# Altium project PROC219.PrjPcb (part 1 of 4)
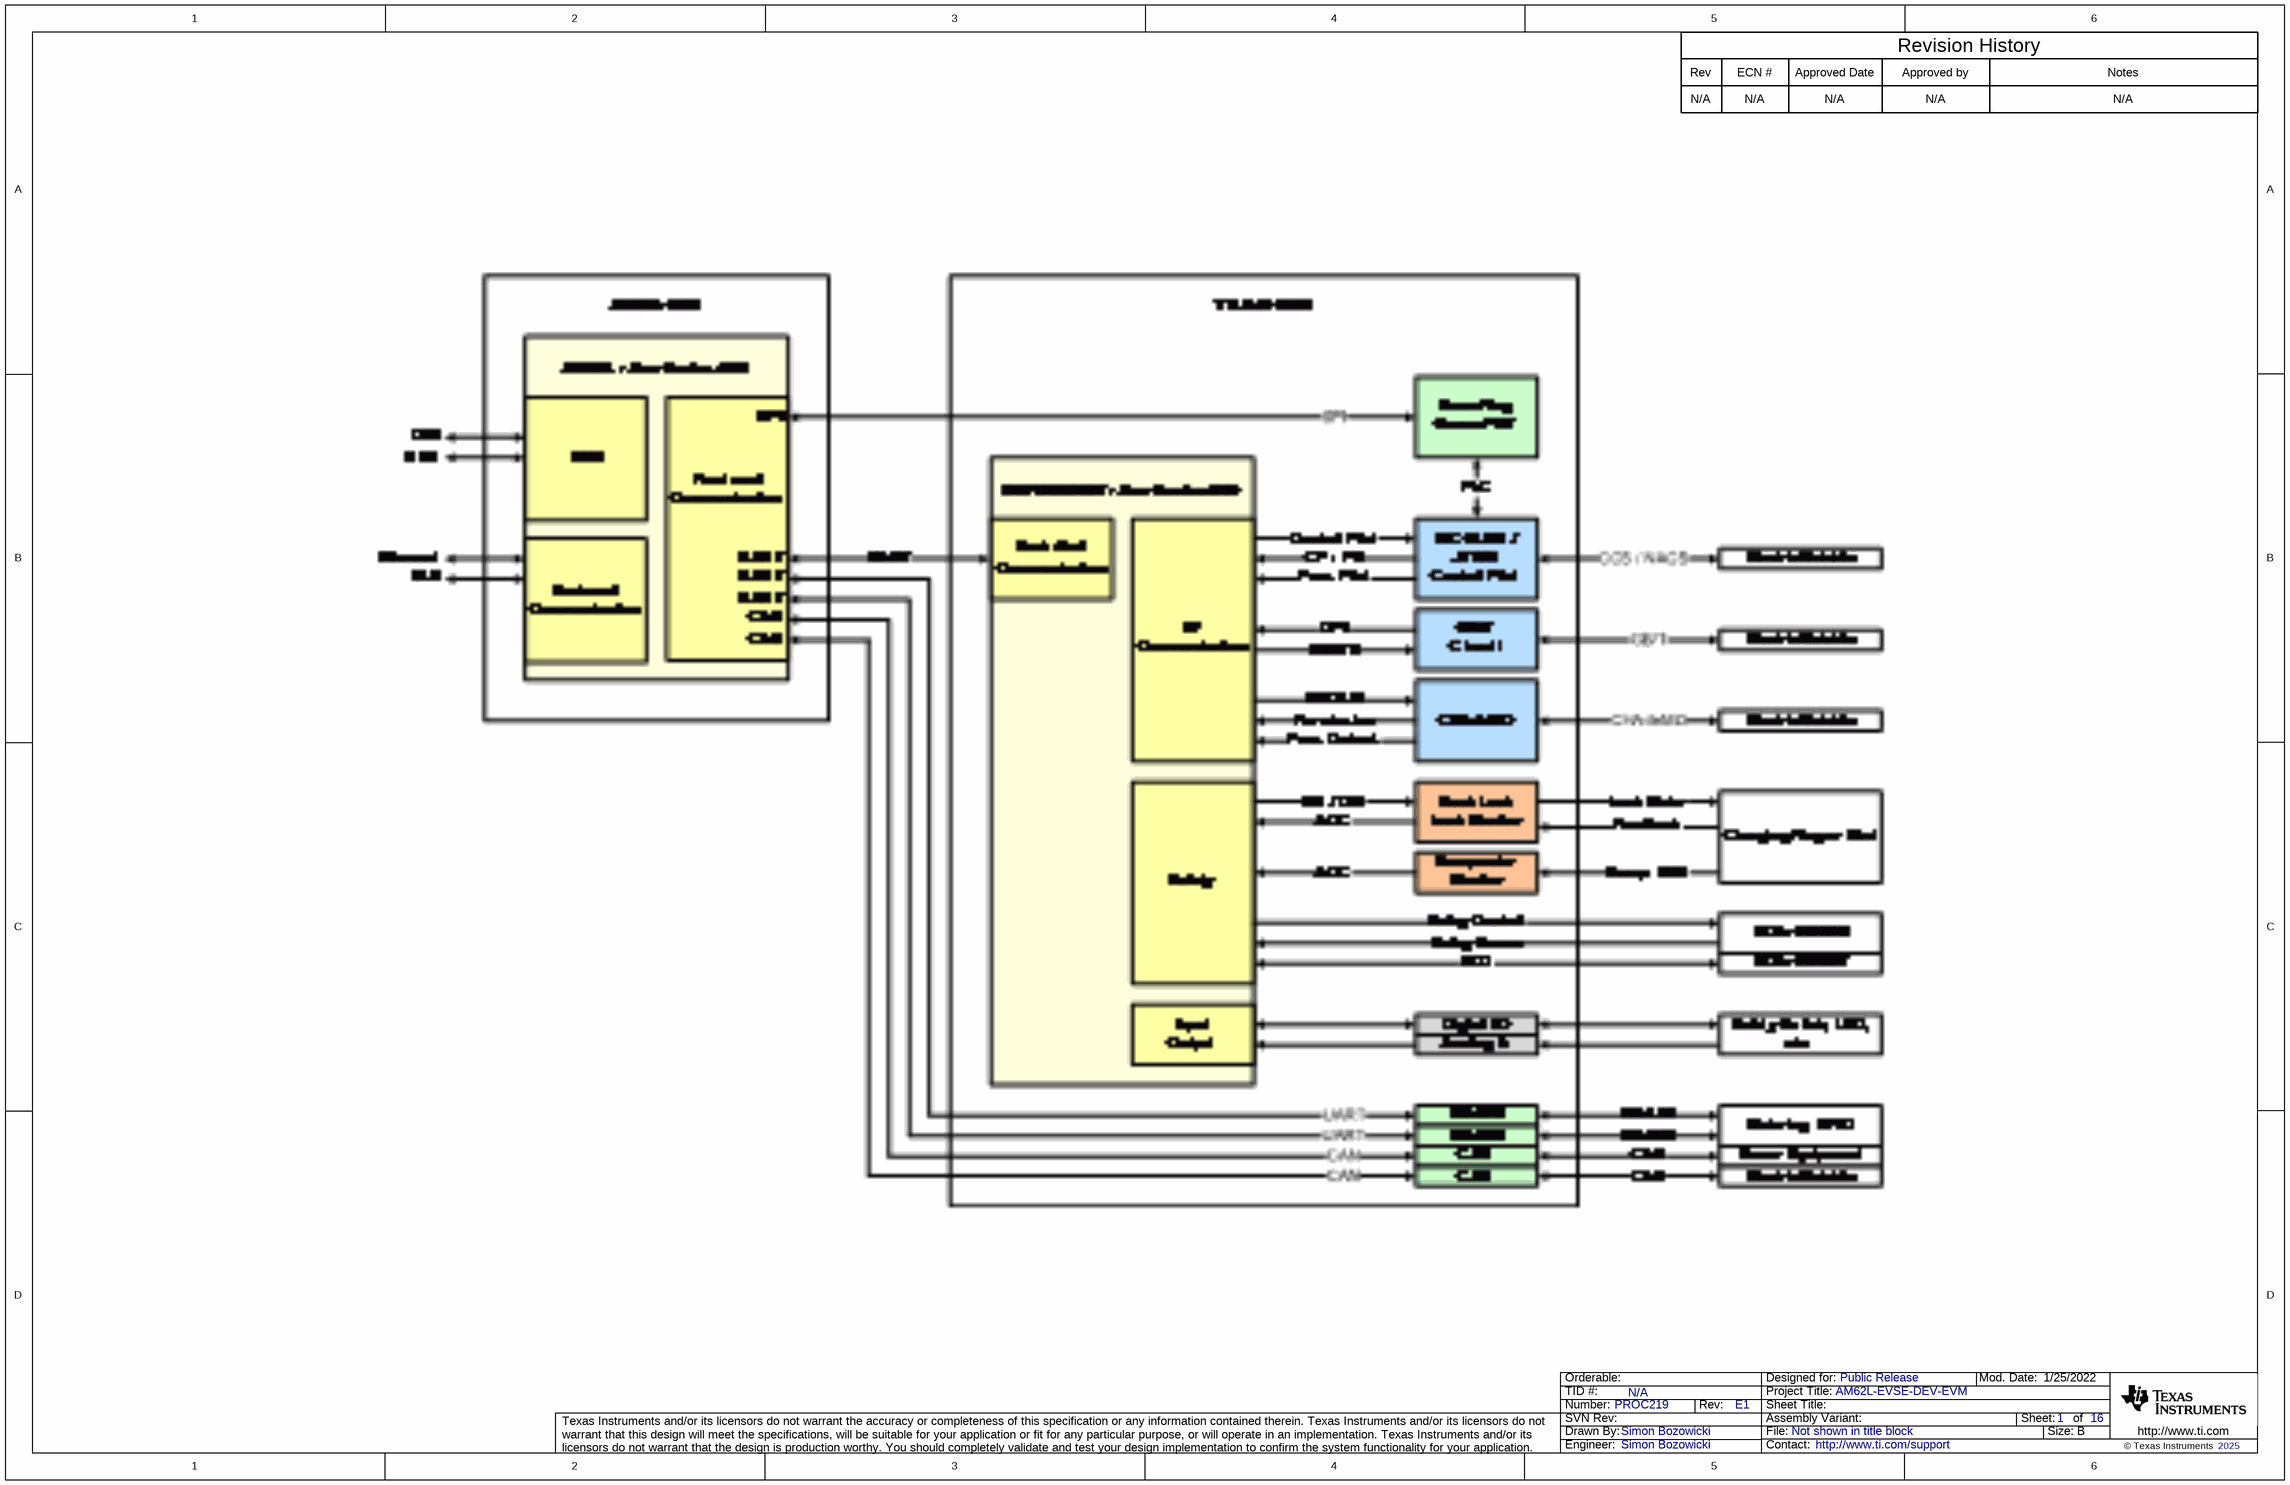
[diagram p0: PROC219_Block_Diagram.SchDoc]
DrawnBy: Simon Bozowicki; TID: N/A; TechSupport: http://www.ti.com/support; SCH_Rev: E1; PRJ_Title: AM62L-EVSE-DEV-EVM; PRJ_Number: PROC219; PRJ_Engineer: Simon Bozowicki; PRJ_Customer: Public Release; PCB_Rev: E1; PCB_Layout: Simon Bozowicki; CopyrightYear: 2025
16 sheets, 580 parts. Net scope: global (net labels, ports and power ports of the same name join across sheets).
Board file: PROC219E1.PcbDoc
Sheets:
  PROC219_Block_Diagram.SchDoc
  PROC219_Power_IN_Dig.SchDoc
  PROC219_Power_Analog.SchDoc
  PROC219_MSPM0.SchDoc
  PROC219_PLC.SchDoc
  PROC219_Pilot_Interface.SchDoc
  PROC219_GBT.SchDoc
  PROC219_CHAdeMO.SchDoc
  PROC219_PluckLock.SchDoc
  PROC219_Temp_Sense.SchDoc
  PROC219_Serial.SchDoc
  PROC219_CAN.SchDoc
  PROC219_IO.SchDoc
  PROC219_XDS110_Debug.SchDoc
  PROC219_Connectors.SchDoc
  PROC219_Hardware.SchDoc

## Sheet PROC219_Block_Diagram.SchDoc
size 431 x 279 mm; Date: Not shown in title block; ApprovedBy: Not shown in title block; CheckedBy: Not shown in title block; Author: Not shown in title block; CompanyName: Not shown in title block; Engineer: Not shown in title block; Organization: Not shown in title block; Address1: Not shown in title block; Address2: Not shown in title block; Address3: Not shown in title block; Address4: Not shown in title block; DocumentNumber: 1; Revision: Use project parameter SCH_Rev; SheetNumber: 1; SheetTotal: 16; PageSetup: Record=PageOptions¦CenterHorizontal=True¦CenterVertical=True¦PrintScale=1.00¦XCorrection=1.00¦YCorrection=1.00¦PrintKind=0¦BorderSize=5000000¦LeftOffset=0¦BottomOffset=0¦Orientation=2¦PaperLength=1000¦PaperWidth=1000¦Scale=100¦PaperSource=15¦PrintQuality=600¦MediaType=1¦DitherType=10¦PaperKind=Letter¦PrintScaleMode=1

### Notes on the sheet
- Rev
- N/A
- ECN #
- Approved Date
- Approved by
- Revision History
- Notes

## Sheet PROC219_Power_IN_Dig.SchDoc
size 431 x 279 mm; Date: Not shown in title block; ApprovedBy: Not shown in title block; CheckedBy: Not shown in title block; Author: Not shown in title block; CompanyName: Not shown in title block; Engineer: Not shown in title block; Organization: Not shown in title block; Address1: Not shown in title block; Address2: Not shown in title block; Address3: Not shown in title block; Address4: Not shown in title block; DocumentNumber: 1; Revision: Use project parameter SCH_Rev; SheetNumber: 2; SheetTotal: 16; PageSetup: Record=PageOptions¦CenterHorizontal=True¦CenterVertical=True¦PrintScale=1.00¦XCorrection=1.00¦YCorrection=1.00¦PrintKind=0¦BorderSize=5000000¦LeftOffset=0¦BottomOffset=0¦Orientation=2¦PaperLength=1000¦PaperWidth=1000¦Scale=100¦PaperSource=15¦PrintQuality=600¦MediaType=1¦DitherType=10¦PaperKind=Letter¦PrintScaleMode=1
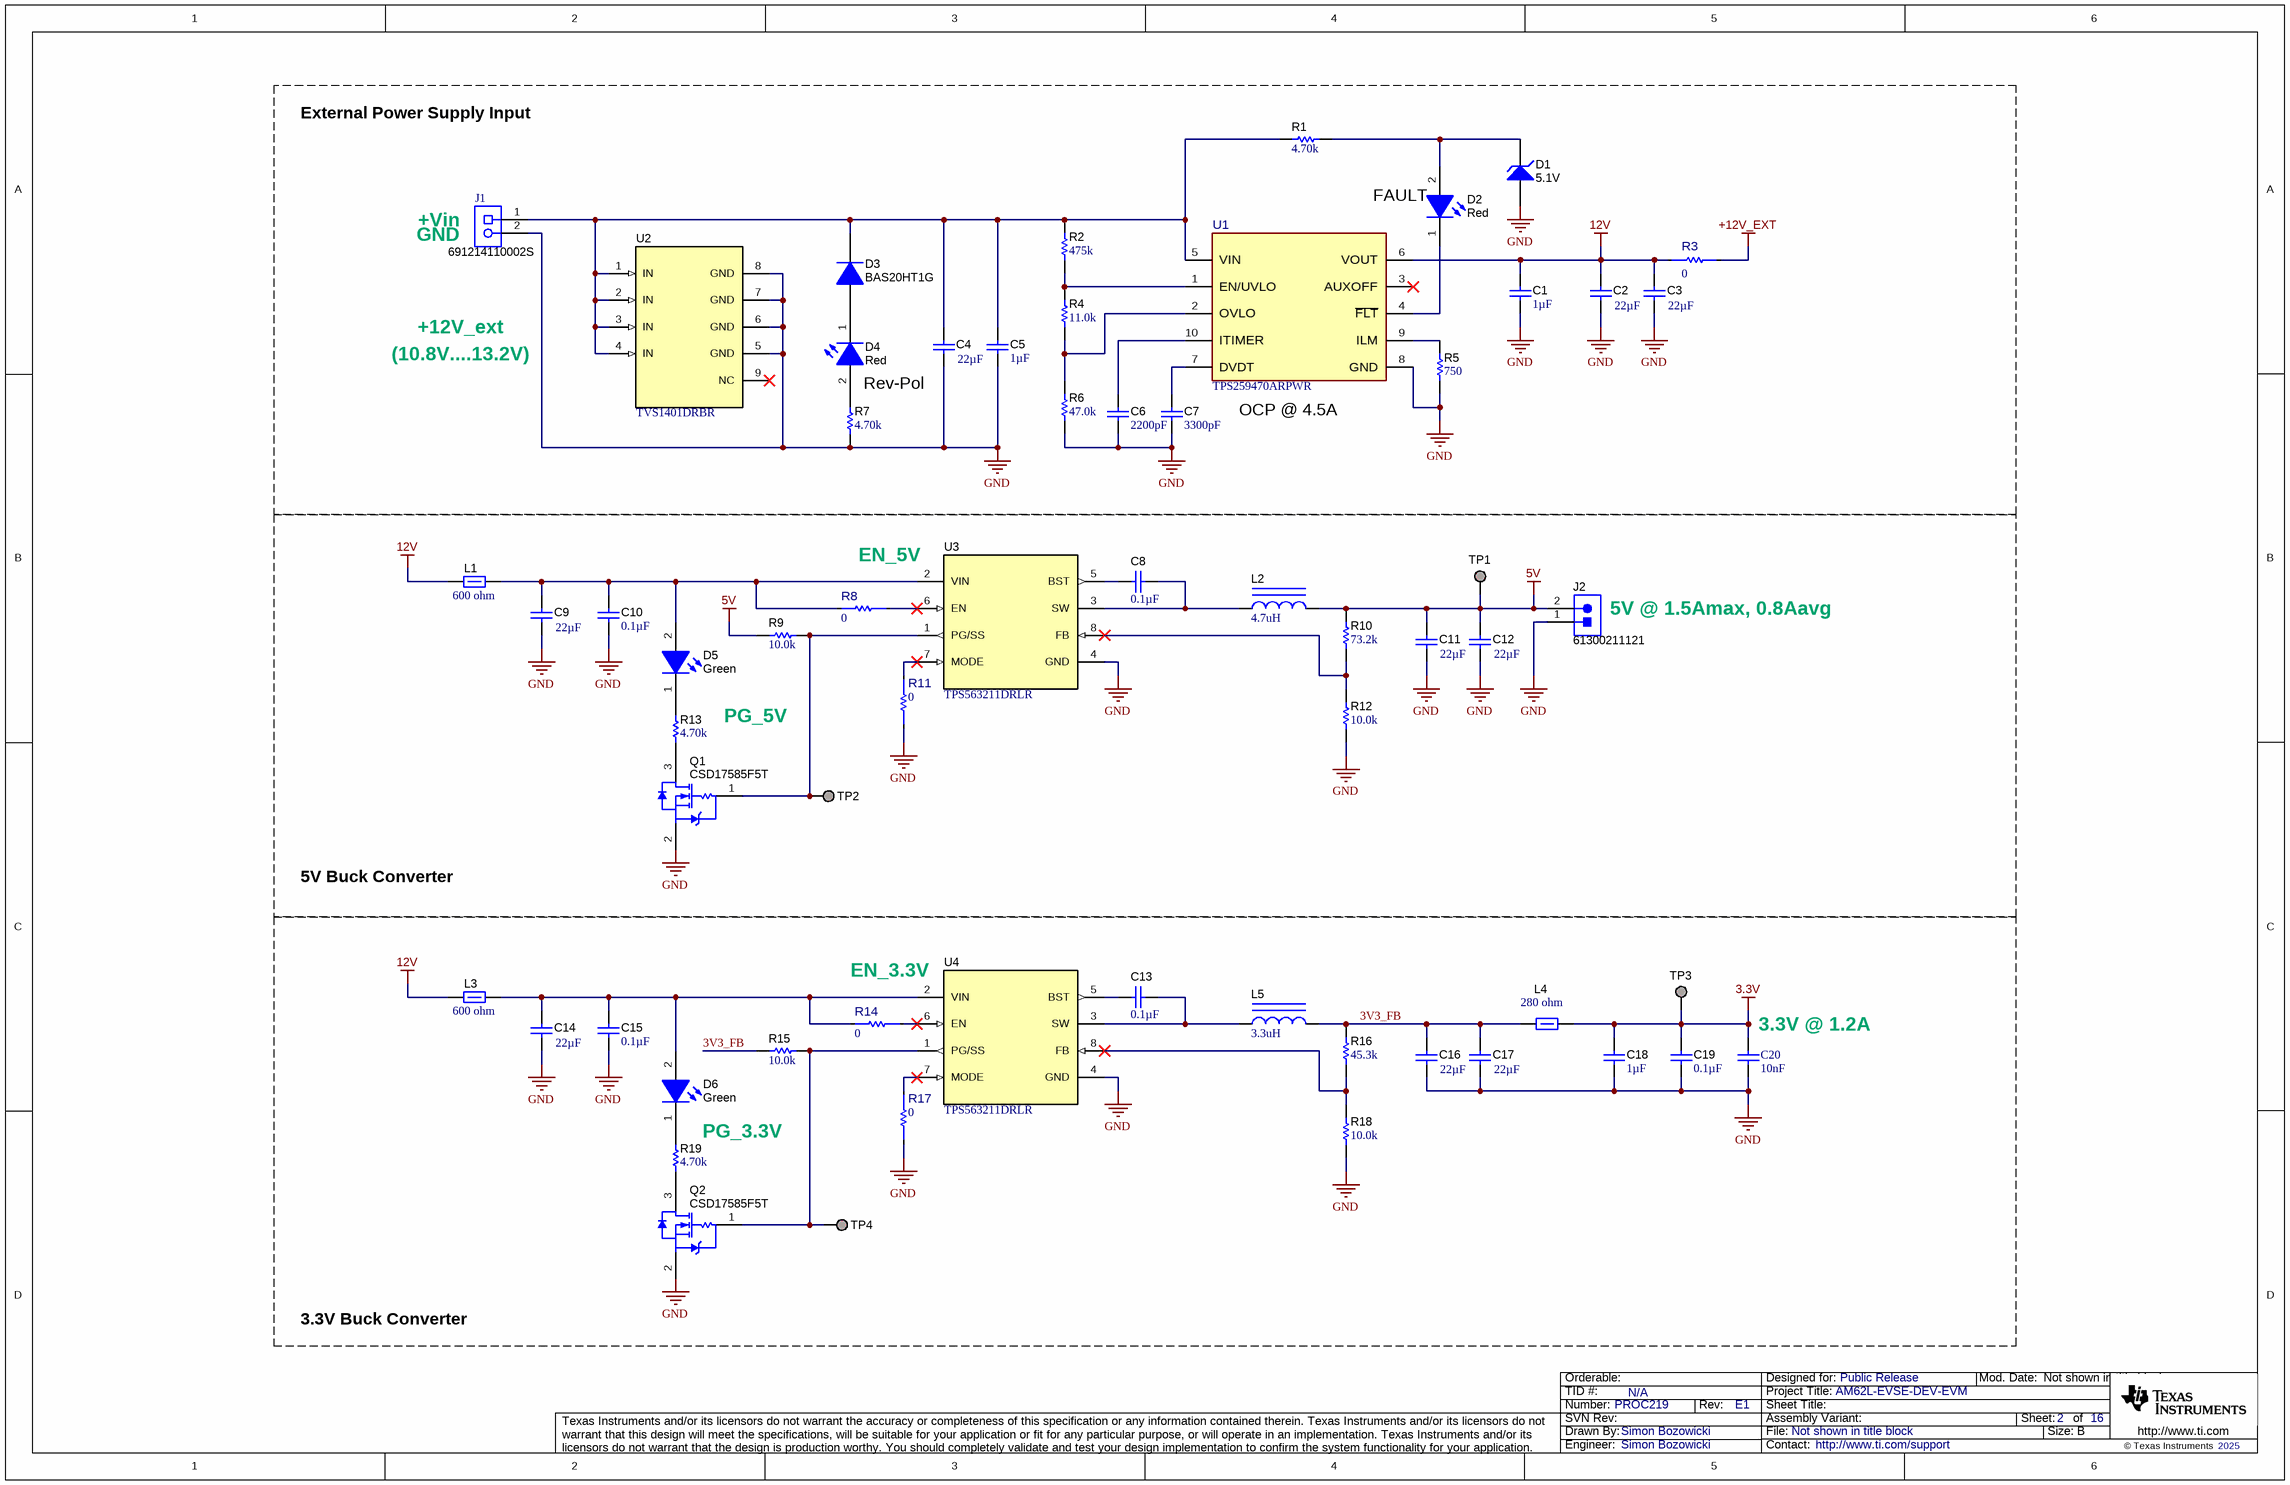
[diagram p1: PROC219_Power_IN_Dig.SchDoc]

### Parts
C1  Cap_F: 1µF  [0603]  (hidden comment: C1608X7R1E105K080AB)
C2  ValueDisplayed: 22µF  [1210_270]  (hidden comment: CC1210KKX7R8BB226)
C3  ValueDisplayed: 22µF  [1210_270]  (hidden comment: CC1210KKX7R8BB226)
C4  ValueDisplayed: 22µF  [1210_270]  (hidden comment: CC1210KKX7R8BB226)
C5  Cap_F: 1µF  [0603]  (hidden comment: C1608X7R1E105K080AB)
C6  ValueDisplayed: 2200pF  [0402]  (hidden comment: CL05B222JB5NNNC)
C7  ValueDisplayed: 3300pF  [0402]  (hidden comment: GRM155R71H332KA01D)
C8  ValueDisplayed: 0.1µF  [0402]  (hidden comment: CC0402KRX7R8BB104)
C9  ValueDisplayed: 22µF  [1210_270]  (hidden comment: CC1210KKX7R8BB226)
C10  ValueDisplayed: 0.1µF  [0402]  (hidden comment: CC0402KRX7R8BB104)
C11  ValueDisplayed: 22µF  [1210_270]  (hidden comment: CC1210KKX7R8BB226)
C12  ValueDisplayed: 22µF  [1210_270]  (hidden comment: CC1210KKX7R8BB226)
C13  ValueDisplayed: 0.1µF  [0402]  (hidden comment: CC0402KRX7R8BB104)
C14  ValueDisplayed: 22µF  [1210_270]  (hidden comment: CC1210KKX7R8BB226)
C15  ValueDisplayed: 0.1µF  [0402]  (hidden comment: CC0402KRX7R8BB104)
C16  ValueDisplayed: 22µF  [1210_270]  (hidden comment: CC1210KKX7R8BB226)
C17  ValueDisplayed: 22µF  [1210_270]  (hidden comment: CC1210KKX7R8BB226)
C18  Cap_F: 1µF  [0603]  (hidden comment: C1608X7R1E105K080AB)
C19  ValueDisplayed: 0.1µF  [0402]  (hidden comment: CC0402KRX7R8BB104)
C20  value 10nF  [WCAP-CSGP_0402_L1W0.5H0.5]  (hidden comment: 885012205050)
D1  value 5.1V  [SOD-523]  (hidden comment: BZT52C5V1T-7)
D2  value Red  [WL-SMCW_RED]  (hidden comment: 150060RS75000)
D3  BAS20HT1G  [SOD-323]
D4  value Red  [WL-SMCW_RED]  (hidden comment: 150060RS75000)
D5  value Green  [WL-SMCW_GREEN]  (hidden comment: 150060VS75000)
D6  value Green  [WL-SMCW_GREEN]  (hidden comment: 150060VS75000)
J1  691214110002S  [FP-691214110002S_HDR2-MFG]
J2  61300211121  [WURTH_61300211121]
L1  value 600 ohm  [1206]  (hidden comment: 74279221601)
L2  ValueDisplayed: 4.7uH  [WE-HC4]  (hidden comment: 744311470)
L3  value 600 ohm  [1206]  (hidden comment: 74279221601)
L4  value 280 ohm  [1206]  (hidden comment: 74279221281)
L5  ValueDisplayed: 3.3uH  [WE-LHMI_7050]  (hidden comment: 74437349033)
Q1  CSD17585F5T  [YJK0003A]
Q2  CSD17585F5T  [YJK0003A]
R1  ValueDisplayed: 4.70k  [0402]  (hidden comment: ERJ-2RKF4701X)
R2  ValueDisplayed: 475k  [0402]  (hidden comment: CRCW0402475KFKED)
R3  value 0  [FP-CRCW12060000Z0EAC_1206-MFG]  (hidden comment: CRCW12060000Z0EAC)
R4  ValueDisplayed: 11.0k  [0402]  (hidden comment: CRCW040211K0FKED)
R5  ValueDisplayed: 750  [0402]  (hidden comment: CRCW0402750RFKED)
R6  ValueDisplayed: 47.0k  [0402]  (hidden comment: RC0402FR-0747KL)
R7  ValueDisplayed: 4.70k  [0402]  (hidden comment: ERJ-2RKF4701X)
R8  value 0  [FP-CRG0402ZR_0402-IPC_C]  (hidden comment: CRG0402ZR)
R9  ValueDisplayed: 10.0k  [0402]  (hidden comment: ERJ-2RKF1002X)
R10  ValueDisplayed: 73.2k  [0402]  (hidden comment: CRCW040273K2FKED)
R11  value 0  [FP-CRG0402ZR_0402-IPC_C]  (hidden comment: CRG0402ZR)
R12  ValueDisplayed: 10.0k  [0402]  (hidden comment: ERJ-2RKF1002X)
R13  ValueDisplayed: 4.70k  [0402]  (hidden comment: ERJ-2RKF4701X)
R14  value 0  [FP-CRG0402ZR_0402-IPC_C]  (hidden comment: CRG0402ZR)
R15  ValueDisplayed: 10.0k  [0402]  (hidden comment: ERJ-2RKF1002X)
R16  ValueDisplayed: 45.3k  [0402S]  (hidden comment: RC0402FR-0745K3L)
R17  value 0  [FP-CRG0402ZR_0402-IPC_C]  (hidden comment: CRG0402ZR)
R18  ValueDisplayed: 10.0k  [0402]  (hidden comment: ERJ-2RKF1002X)
R19  ValueDisplayed: 4.70k  [0402]  (hidden comment: ERJ-2RKF4701X)
TP1  TP_SM_1MM  [TP_SM_1MM]  (value not drawn)  (no BOM)
TP2  TP_SM_1MM  [TP_SM_1MM]  (value not drawn)  (no BOM)
TP3  TP_SM_1MM  [TP_SM_1MM]  (value not drawn)  (no BOM)
TP4  TP_SM_1MM  [TP_SM_1MM]  (value not drawn)  (no BOM)
U1  TPS259470ARPWR  [RPW0010A-MFG]
U2  TVS1401DRBR  [DRB0008A]
U3  TPS563211DRLR  [DRL0008A]
U4  TPS563211DRLR  [DRL0008A]

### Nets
3.3V: C18.1 C19.1 C20.1 L4.2 TP3.1
5V: C11.2 C12.2 J2.2 L2.2 R9.2 R10.2 TP1.1
12V: C1.1 C2.2 C3.2 L1.1 L3.1 R3.1 U1.6(VOUT)
+12V_EXT: R3.2
GND: C1.2 C2.1 C3.1 C4.1 C5.2 C6.2 C7.2 C9.1 C10.2 C11.1 C12.1 C14.1 C15.2 C16.1 C17.1 C18.2 C19.2 C20.2 D1.2(A) J1.2 J2.1 Q1.2(S) Q2.2(S) R5.1 R6.1 R7.2 R11.2 R12.1 R17.2 R18.1 U1.8(GND) U2.5(GND) U2.6(GND) U2.7(GND) U2.8(GND) U3.4(GND) U4.4(GND)
3V3_FB: C16.2 C17.2 L4.1 L5.2 R15.2 R16.2
NetC4_2: C4.2 C5.1 D3.1(K) J1.1 R1.2 R2.2 U1.5(VIN) U2.1(IN) U2.2(IN) U2.3(IN) U2.4(IN)
NetC6_1: C6.1 U1.10(ITIMER)
NetC7_1: C7.1 U1.7(DVDT)
NetC8_1: C8.1 U3.5(BST)
NetC8_2: C8.2 L2.1 U3.3(SW)
NetC9_2: C9.2 C10.1 D5.2(A) L1.2 R8.2 U3.2(VIN)
NetC13_1: C13.1 U4.5(BST)
NetC13_2: C13.2 L5.1 U4.3(SW)
NetC14_2: C14.2 C15.1 D6.2(A) L3.2 R14.2 U4.2(VIN)
NetD1_1: D1.1(K) D2.2(A) R1.1
NetD2_1: D2.1(K) U1.4(~{FLT})
NetD3_2: D3.2(A) D4.1(K)
NetD4_2: D4.2(A) R7.1
NetD5_1: D5.1(K) R13.1
NetD6_1: D6.1(K) R19.1
NetQ1_1: Q1.1(G) R9.1 TP2.1 U3.1(PG/SS)
NetQ1_3: Q1.3(D) R13.2
NetQ2_1: Q2.1(G) R15.1 TP4.1 U4.1(PG/SS)
NetQ2_3: Q2.3(D) R19.2
NetR2_1: R2.1 R4.2 U1.1(EN/UVLO)
NetR4_1: R4.1 R6.2 U1.2(OVLO)
NetR5_2: R5.2 U1.9(ILM)
NetR8_1: R8.1 U3.6(EN)
NetR10_1: R10.1 R12.2 U3.8(FB)
NetR11_1: R11.1 U3.7(MODE)
NetR14_1: R14.1 U4.6(EN)
NetR16_1: R16.1 R18.2 U4.8(FB)
NetR17_1: R17.1 U4.7(MODE)

Not connected (* = marked no-connect by the designer): U1 3(AUXOFF)*; U2 9(NC)*

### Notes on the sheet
- External Power Supply Input
- (near J1) +Vin
- (near D2) FAULT
- (near J1) GND
- +12V_ext
- (10.8V....13.2V)
- Rev-Pol
- (near U1) OCP @ 4.5A
- EN_5V
- (near J2) 5V @ 1.5Amax, 0.8Aavg
- PG_5V
- 5V Buck Converter
- (near U4) EN_3.3V
- (near C20) 3.3V @ 1.2A
- PG_3.3V
- 3.3V Buck Converter

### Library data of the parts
C1 C5 C18 = CMP-0007040-4: CAP, CERM, 1 uF, 25 V, +/- 10%, X7R, 0603; Manufacturer: TDK; TaMin_C: -55°C; Polarized: N; SizeAreaWB_mm2: 4.68; Value1: Unknown; U/M: EA; Value: 1uF; TaMax_C: 125°C; SizeZ_mm: 1; SizeX_mm: 1.6; SizeY_mm: 0.8; Value2: 25V; SizeArea_mm2: 1.28; AEC Category: Q200
C2-C4 C9 C11 C12 C14 C16 C17 = CMP-0082267-1: CAP, CERM, 22 µF, 25 V,+/- 10%, X7R, 1210; Manufacturer: Yageo; TaMin_C: -55°C; ESR_ohm: 1m; Polarized: N; SizeAreaWB_mm2: 14.7; Value1: 0.001 ohm; U/M: EA; Value: 22uF; TaMax_C: 125°C; SizeZ_mm: 2.7; SizeX_mm: 3.2; SizeY_mm: 2.5; Cap_Case: 1210; Value2: 25V; SizeArea_mm2: 8; AEC Category: Q200
C6 = CMP-0006344-2: CAP, CERM, 2200 pF, 50 V, +/- 5%, X7R, 0402; Manufacturer: Samsung Electro-Mechanics; TaMin_C: -55°C; Polarized: N; SizeAreaWB_mm2: 3; Value1: Unknown; U/M: EA; Value: 2200pF; TaMax_C: 125°C; SizeZ_mm: 0.6; SizeX_mm: 1; SizeY_mm: 0.5; Value2: 50V; Cap_F: 2.2nF; AEC Category: Q200
C7 = CMP-0006688-2: CAP, CERM, 3300 pF, 50 V, +/- 10%, X7R, 0402; Manufacturer: MuRata; TaMin_C: -55°C; Polarized: N; SizeAreaWB_mm2: 3; Value1: Unknown; U/M: EA; Value: 3300pF; TaMax_C: 125°C; SizeZ_mm: 0.6; SizeX_mm: 1; SizeY_mm: 0.5; Value2: 50V; Cap_F: 3.3nF; AEC Category: Q200
C8 C10 C13 C15 C19 = CMP-0860555-1: CAP, CERM, 0.1 µF, 25 V,+/- 10%, X7R, 0402; Manufacturer: Yageo; SizeArea_mm2: 0.5; AEC Qualified: N; SizeX_mm: 1; U/M: EA; Value: 0.1uF; TaMin_C: -55°C; VDC_V: 25V; SizeZ_mm: 0.6; Cap_F: 100nF; TaMax_C: 125°C; SizeAreaWB_mm2: 3; AEC Category: Q200
C20 = CMP-0052806-1: WCAP-CSGP Multilayer Ceramic Chip Capacitor, General Purpose, size 0402, X7R, 10nF, 25VDC; Manufacturer: Wurth Elektronik; Capacitance Tolerance: +/-10%; Dissipation Factor: 3.5%; Insulation Resistance: 10GOhm; Rated Voltage (DC): 25V; Technical Reference: X7R0402103K025DFCT10000
D1 = CMP-0005899-4: Diode, Zener, 5.1 V, 300 mW, SOD-523; Manufacturer: Diodes Inc.; Power_W: 300mW; Value1: 0.3W; SizeZ_mm: 0.65; AEC Category: Q101; SizeX_mm: 1.7; RJA_CperW: 417; SizeArea_mm2: 1.53; SizeY_mm: 0.9; SizeAreaWB_mm2: 5.13
D2 D4 = CMP-0002947-3: LED, Red, SMD; Manufacturer: Wurth Elektronik; Value1: 0.072W; Vf_V: 2V; Angle: 140; Tjmax_C: 85°C; Type: AlInGaP; Vr_V: 5V; Io_A: 30mA; Power_TotalModule: 72mW
D3 = CMP-0029150-2: Diode, Switching, 200 V, 0.2 A, AEC-Q101, SOD-323; Manufacturer: ON Semiconductor; Value2: 1.25V; Value1: 0.2A; SizeZ_mm: 1; Green_REACh: Incomplete; SizeArea_mm2: 3.645; Vr_V: 200V; SizeX_mm: 2.7; TJmax_C: 150°C; Io_A: 200mA; Value: 200V; Green_Lifecycle: Not Set; SizeAreaWB_mm2: 8.695; AEC Qualified: Y; AEC Category: Q101; SizeY_mm: 1.35
D5 D6 = CMP-0002894-2: LED, Green, SMD; Manufacturer: Wurth Elektronik; Type: AlInGaP; Value2: 2V; Io_A: 20mA; Value1: W
J1 = CMP-0093089-2: 2 Position Wire to Board Terminal Block Horizontal with Board 0.138" (3.50mm) Through Hole; Manufacturer: Wurth; ContactFinish: Tin,Nickel; AEC Qualified: No; Max Wire Gauge: 16; Voltage_V: 300V; SizeZ_mm: 9.2mm; Current_A: 10A; DUT-Pitch_mm: 3.5mm; Min Wire Gauge: 30; Conn Gender: Female; Row_Count: 1; Is Female: yes
J2 = CMP-0054794-2: Header, 2.54 mm, 2x1, Gold, TH; Manufacturer: Wurth Elektronik; Shrouded: N; Gender: Male; Green_REACh: Passed; Pitch_mm: 2.54; Green_Lifecycle: Active; Row_Count: 1; Cert_UL: Y
L1 L3 = CMP-0003141-1: Ferrite Bead, 600 ohm @ 100 MHz, 2.5 A, 1206; Manufacturer: Wurth Elektronik; Ztyp@1GHz_Ohm: 83.8; ZTyp@100MHz_Ohm: 600; SizeAreaWB_mm2: 10.92; DCR_ohm: 38m; Value1: 0.038 ohm; Imax_A: 2.5A; SizeZ_mm: 1.35; SizeX_mm: 3.2; SizeY_mm: 1.6; SizeArea_mm2: 5.12
L2 = CMP-0063928-1: Inductor, Shielded Drum Core, Superflux, 4.7 uH, 6 A, 0.02 ohm, SMD; Manufacturer: Wurth Elektronik; Isat: 7A @ 30% inductance drop; Irms: 6A @ 50C rise; Green_Lifecycle: Active; SizeAreaWB_mm2: 80.1; DCR_ohm: 20m; Green_REACh: Passed; Value: 4.7uH; Imax_A: 6A; SizeZ_mm: 4; SizeX_mm: 7; SizeY_mm: 6.9; SizeArea_mm2: 48.3; Ind_H: 4.7µH; AEC Category: Q200
L4 = CMP-0003140-1: Ferrite Bead, 280 ohm @ 100 MHz, 3.5 A, 1206; Manufacturer: Wurth Elektronik; Ztyp@1GHz_Ohm: 79.415; ZTyp@100MHz_Ohm: 280; SizeAreaWB_mm2: 10.92; DCR_ohm: 22m; Value1: 0.022 ohm; Imax_A: 3.5A; SizeZ_mm: 1.35; SizeX_mm: 3.2; SizeY_mm: 1.6; SizeArea_mm2: 5.12
L5 = CMP-0064107-1: Inductor, Shielded Drum Core, Powdered Iron, 3.3 uH, 6 A, 0.019 ohm, SMD; Manufacturer: Wurth Elektronik; Isat: 12A @ 20% inductance drop; Irms: 6A @ 40C rise; Green_Lifecycle: Active; SizeAreaWB_mm2: 73.96; DCR_ohm: 19m; Green_REACh: Passed; Value: 3.3uH; Imax_A: 6A; SizeZ_mm: 5; SizeX_mm: 6.6; SizeArea_mm2: 43.56; Ind_H: 3.3µH; AEC Category: Q200
Q1 Q2 = CMP-0067551-1: MOSFET, N-CH, 30 V, 5.9 A, YJK0003A (PICOSTAR-3); Alternate Manufacturer: None; Manufacturer: Texas Instruments; Rdson45_ohm: 0.033; QgTyp_nC: 1.9; SizeAreaWB_mm2: 4.3077; Vgs_V: 20V; Value1: 0.033 ohm; VdsMax_V: 30V; U/M: EA; Value: 30V; IdsMax_A: 5.9A; SizeZ_mm: 0.35; SizeX_mm: 1.49; SizeY_mm: 0.73; Value2: 1.9 nC; SizeArea_mm2: 1.0877; ChType: N; AEC Category: Q101
R1 R7 R13 R19 = CMP-0026700-1: RES, 4.70 k, 1%, 0.1 W, 0402; Manufacturer: Panasonic; Power_W: 100mW; TempCo: 100 ppm/C; Value_Code: 4k70; U/M: EA; Value: 4.70k; Res_ohm: 4.7k; SizeX_mm: 1; SizeY_mm: 0.5; SizeZ_mm: 0.6; Value2: 0.1W; VDC_V: 50V; AEC Category: Q200
R2 = CMP-0026393-2: RES, 475 k, 1%, 0.063 W, AEC-Q200 Grade 0, 0402; Manufacturer: Vishay-Dale; Power_W: 63mW; TempCo: 100 ppm/C; Value: 475k; EIA_Code: E96; SizeX_mm: 1; SizeY_mm: 0.5; SizeZ_mm: 0.6; Value2: 0.063W; AEC Qualified: Y; VDC_V: 50V; AEC Category: Q200; AEC Grade: 0
R3 = CMP-0094724-1: Jumper 0.25W, 1/4W Chip Resistor 1206 (3216 Metric) - Thick Film; Manufacturer: Vishay; SizeZ_mm: 0.65mm; Power_W: 250mW; VDC_V: 200V; AEC Qualified: No
R4 = CMP-0025975-3: RES, 11.0 k, 1%, 0.063 W, AEC-Q200 Grade 0, 0402; Manufacturer: Vishay-Dale; Power_W: 63mW; TempCo: 100 ppm/C; Value_Code: 11k0; Value: 11.0k; EIA_Code: E96; Res_ohm: 11k; SizeX_mm: 1; SizeY_mm: 0.5; SizeZ_mm: 0.6; Value2: 0.063W; AEC Qualified: Y; VDC_V: 50V; AEC Category: Q200; AEC Grade: 0
R5 = CMP-0026542-2: RES, 750, 1%, 0.063 W, AEC-Q200 Grade 0, 0402; Manufacturer: Vishay-Dale; Power_W: 63mW; TempCo: 100 ppm/C; Value_Code: 750R; Value: 750; EIA_Code: E96; SizeX_mm: 1; SizeY_mm: 0.5; SizeZ_mm: 0.6; Value2: 0.063W; AEC Qualified: Y; VDC_V: 50V; AEC Grade: 0; AEC Category: Q200
R6 = CMP-0026737-1: RES, 47.0 k, 1%, 0.0625 W, 0402; Manufacturer: Yageo America; Power_W: 62.5mW; TempCo: 100 ppm/C; Value_Code: 47k0; U/M: EA; Value: 47.0k; Res_ohm: 47k; SizeX_mm: 1; SizeY_mm: 0.5; SizeZ_mm: 0.6; AEC Qualified: N; VDC_V: 50V; AEC Category: Q200
R8 R11 R14 R17 = CMP-0095664-1: Jumper 0.063W, 1/16W Chip Resistor 0402 (1005 Metric) - Thick Film; Manufacturer: TE Connectivity; SizeZ_mm: 0.4mm; VDC_V: 50V; TempCo: 200ppm/°C; Power_W: 62.5mW; AEC Qualified: No
R9 R12 R15 R18 = CMP-0026658-1: RES, 10.0 k, 1%, 0.1 W, 0402; Manufacturer: Panasonic; Power_W: 100mW; TempCo: 100 ppm/C; Value_Code: 10k0; U/M: EA; Value: 10.0k; EIA_Code: E96; Res_ohm: 10k; SizeX_mm: 1; SizeY_mm: 0.5; SizeZ_mm: 0.6; Value2: 0.1W; VDC_V: 50V; AEC Category: Q200
R10 = CMP-0026539-2: RES, 73.2 k, 1%, 0.063 W, AEC-Q200 Grade 0, 0402; Manufacturer: Vishay-Dale; Power_W: 63mW; TempCo: 100 ppm/C; Value_Code: 73k2; Value: 73.2k; EIA_Code: E96; SizeX_mm: 1; SizeY_mm: 0.5; SizeZ_mm: 0.6; Value2: 0.063W; AEC Qualified: Y; VDC_V: 50V; AEC Category: Q200; AEC Grade: 0
R16 = CMP-0077552-1: RES, 45.3 k, 1%, 0.063 W, 0402; Manufacturer: Yageo America; Value_Code: 45k3; SizeArea_mm2: 0.5; AEC Qualified: N; AEC Category: Q200; Value: 45.3k; SizeZ_mm: 0.6; EIA_Code: E96; TempCo: 100 ppm/C; Power_W: 63mW; VDC_V: 50V; Value2: 0.063W; U/M: EA; SizeX_mm: 1.0
TP1-TP4 = CMP-0003825-1: 1mm Test Point, SMT; Manufacturer: Any
U1 = CMP-0091660-1: 2.7 - 23 V, 5.5 A, 28 mΩ True Reverse Current Blocking eFuse with Input Reverse Polarity Protection; Manufacturer: Texas Instruments; Min Supply Voltage: 2.7V; TJmax_C: +125°C; Nominal Supply Current: 428uA; Max Supply Voltage: 23V; SizeZ_mm: 1mm; AEC Qualified: No; Standoff Height: 0mm; Number Of Outputs: 1
U2 = CMP-0083940-3: 14 V Bidirectional Flat-Clamp Surge Protection Device, DRB0008A (VSON-8); Alternate PartNumber: TVS1401DRBT; Alternate Manufacturer: Texas Instruments; CompType: IC; SizeAreaWB_mm2: 16.0; SizeZ_mm: 1.0; SizeY_mm: 3.0; AEC Category: Q200; SizeArea_mm2: 9.0; AEC Qualified: N
U3 U4 = CMP-0861058-2: 4.2-V to 17-V Input, 3-A Synchronous Buck Converter, DRL0008A (SOT-5X3-8); Alternate Manufacturer: Texas Instruments; AEC Category: Q200; SizeAreaWB_mm2: 8.06; SizeArea_mm2: 3.36; CompType: IC; SizeZ_mm: 0.6; AEC Qualified: N; SizeY_mm: 2.1; SizeX_mm: 1.6

## Sheet PROC219_Power_Analog.SchDoc
size 431 x 279 mm; Date: Not shown in title block; ApprovedBy: Not shown in title block; CheckedBy: Not shown in title block; Author: Not shown in title block; CompanyName: Not shown in title block; Engineer: Not shown in title block; Organization: Not shown in title block; Address1: Not shown in title block; Address2: Not shown in title block; Address3: Not shown in title block; Address4: Not shown in title block; DocumentNumber: 2; Revision: Use project parameter SCH_Rev; SheetNumber: 3; SheetTotal: 16; PageSetup: Record=PageOptions¦CenterHorizontal=True¦CenterVertical=True¦PrintScale=1.00¦XCorrection=1.00¦YCorrection=1.00¦PrintKind=0¦BorderSize=5000000¦LeftOffset=0¦BottomOffset=0¦Orientation=2¦PaperLength=1000¦PaperWidth=1000¦Scale=100¦PaperSource=15¦PrintQuality=600¦MediaType=1¦DitherType=10¦PaperKind=Letter¦PrintScaleMode=1
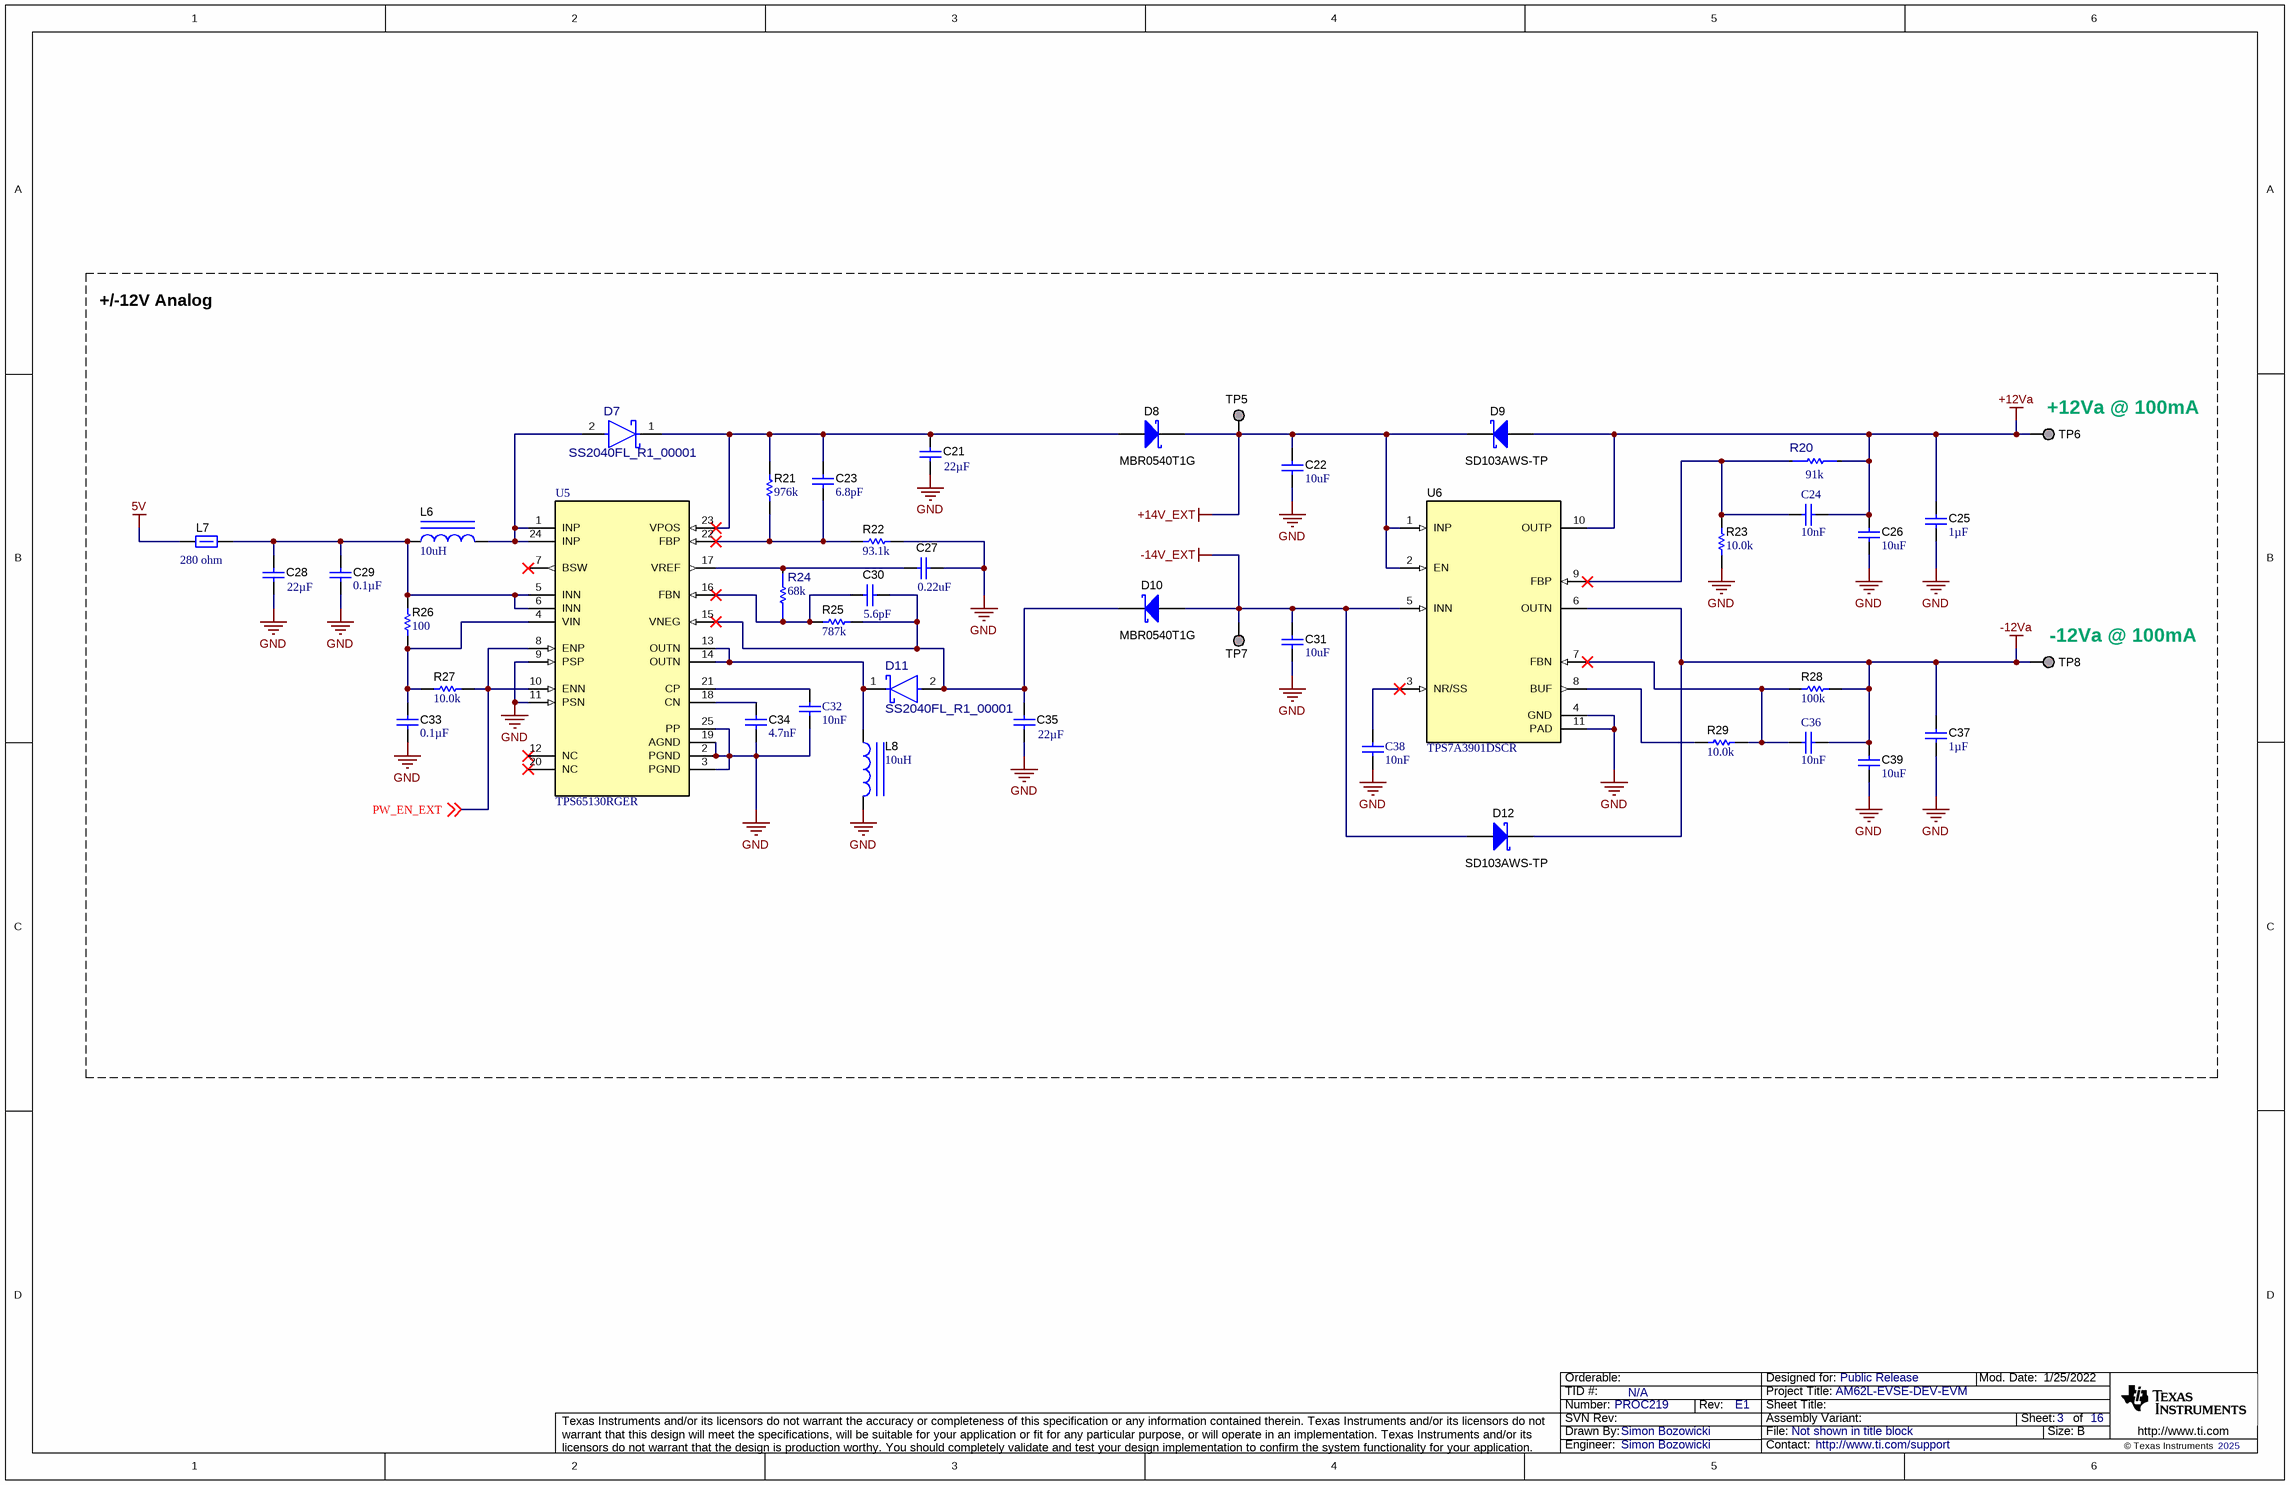
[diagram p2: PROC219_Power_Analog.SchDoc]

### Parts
C21  ValueDisplayed: 22µF  [1210_270]  (hidden comment: CC1210KKX7R8BB226)
C22  ValueDisplayed: 10uF  [1206_180]  (hidden comment: CL31B106KBHNNNE)
C23  ValueDisplayed: 6.8pF  [0402]  (hidden comment: GRM1555C1H6R8CA01D)
C24  value 10nF  [WCAP-CSGP_0402_L1W0.5H0.5]  (hidden comment: 885012205050)
C25  Cap_F: 1µF  [0603]  (hidden comment: C1608X7R1E105K080AB)
C26  ValueDisplayed: 10uF  [1206_180]  (hidden comment: CL31B106KBHNNNE)
C27  ValueDisplayed: 0.22uF  [0402]  (hidden comment: C1005X7R1C224K050BC)
C28  ValueDisplayed: 22µF  [1210_270]  (hidden comment: CC1210KKX7R8BB226)
C29  ValueDisplayed: 0.1µF  [0402]  (hidden comment: CC0402KRX7R8BB104)
C30  ValueDisplayed: 5.6pF  [0402]  (hidden comment: GRM1555C1H5R6CA01D)
C31  ValueDisplayed: 10uF  [1206_180]  (hidden comment: CL31B106KBHNNNE)
C32  value 10nF  [WCAP-CSGP_0402_L1W0.5H0.5]  (hidden comment: 885012205050)
C33  ValueDisplayed: 0.1µF  [0402]  (hidden comment: CC0402KRX7R8BB104)
C34  value 4.7nF  [WCAP-CSGP_0402_L1W0.5H0.5]  (hidden comment: 885012205065)
C35  ValueDisplayed: 22µF  [1210_270]  (hidden comment: CC1210KKX7R8BB226)
C36  value 10nF  [WCAP-CSGP_0402_L1W0.5H0.5]  (hidden comment: 885012205050)
C37  Cap_F: 1µF  [0603]  (hidden comment: C1608X7R1E105K080AB)
C38  value 10nF  [WCAP-CSGP_0402_L1W0.5H0.5]  (hidden comment: 885012205050)
C39  ValueDisplayed: 10uF  [1206_180]  (hidden comment: CL31B106KBHNNNE)
D7  SS2040FL_R1_00001  [FP-SS2040FL_R1_00001_SOD123FL-MFG]
D8  MBR0540T1G  [SOD-123]
D9  SD103AWS-TP  [SOD-323]
D10  MBR0540T1G  [SOD-123]
D11  SS2040FL_R1_00001  [FP-SS2040FL_R1_00001_SOD123FL-MFG]
D12  SD103AWS-TP  [SOD-323]
L6  ValueDisplayed: 10uH  [WE-TPC-M1]  (hidden comment: 744042100)
L7  value 280 ohm  [1206]  (hidden comment: 74279221281)
L8  ValueDisplayed: 10uH  [WE-TPC-M1]  (hidden comment: 744042100)
R20  value 91k  [FP-RC0402FR-1391KL_0402-IPC_A]  (hidden comment: RC0402FR-1391KL)
R21  ValueDisplayed: 976k  [0402]  (hidden comment: CRCW0402976KFKED)
R22  ValueDisplayed: 93.1k  [0402]  (hidden comment: CRCW040293K1FKED)
R23  ValueDisplayed: 10.0k  [0402]  (hidden comment: ERJ-2RKF1002X)
R24  value 68k  [FP-WR04X6802FTL_0402-MFG]  (hidden comment: WR04X6802FTL)
R25  ValueDisplayed: 787k  [0402]  (hidden comment: CRCW0402787KFKED)
R26  ValueDisplayed: 100  [0402]  (hidden comment: ERJ-2RKF1000X)
R27  ValueDisplayed: 10.0k  [0402]  (hidden comment: ERJ-2RKF1002X)
R28  ValueDisplayed: 100k  [0402]  (hidden comment: RC0402FR-07100KL)
R29  ValueDisplayed: 10.0k  [0402]  (hidden comment: ERJ-2RKF1002X)
TP5  TP_SM_1MM  [TP_SM_1MM]  (value not drawn)  (no BOM)
TP6  TP_SM_1MM  [TP_SM_1MM]  (value not drawn)  (no BOM)
TP7  TP_SM_1MM  [TP_SM_1MM]  (value not drawn)  (no BOM)
TP8  TP_SM_1MM  [TP_SM_1MM]  (value not drawn)  (no BOM)
U5  TPS65130RGER  [RGE0024B]
U6  TPS7A3901DSCR  [DSC0010J]

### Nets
5V: L7.1
+12Va: C24.2 C25.2 C26.1 D9.2(A) R20.2 TP6.1 U6.10(OUTP)
+14V_EXT: C22.1 D8.1(K) D9.1(K) TP5.1 U6.1(INP) U6.2(EN)
-12Va: C36.2 C37.2 C39.1 D12.1(K) R28.2 TP8.1 U6.6(OUTN)
-14V_EXT: C31.1 D10.2(A) D12.2(A) TP7.1 U6.5(INN)
GND: C21.1 C22.2 C25.1 C26.2 C27.1 C28.1 C29.2 C31.2 C32.2 C33.2 C34.2 C35.1 C37.1 C38.1 C39.2 L8.2 R22.2 R23.2 U5.2(PGND) U5.3(PGND) U5.9(PSP) U5.11(PSN) U5.19(AGND) U5.25(PP) U6.4(GND) U6.11(PAD)
PW_EN_EXT: R27.1 U5.8(ENP) U5.10(ENN) ; off-sheet PW_EN_EXT
NetC21_2: C21.2 C23.1 D7.1(Cathode) D8.2(A) R21.2 U5.23(VPOS)
NetC23_2: C23.2 R21.1 R22.1 U5.22(FBP)
NetC24_1: C24.1 R20.1 R23.1 U6.9(FBP)
NetC27_2: C27.2 R24.2 U5.17(VREF)
NetC28_2: C28.2 C29.1 L6.1 L7.2 R26.2 U5.5(INN) U5.6(INN)
NetC30_1: C30.1 C35.2 D10.1(K) D11.2(Anode) R25.2 U5.15(VNEG)
NetC30_2: C30.2 R24.1 R25.1 U5.16(FBN)
NetC32_1: C32.1 U5.21(CP)
NetC33_1: C33.1 R26.1 R27.2 U5.4(VIN)
NetC34_1: C34.1 U5.18(CN)
NetC36_1: C36.1 R28.1 R29.1 U6.7(FBN)
NetC38_2: C38.2 U6.3(NR/SS)
NetD7_2: D7.2(Anode) L6.2 U5.1(INP) U5.24(INP)
NetD11_1: D11.1(Cathode) L8.1 U5.13(OUTN) U5.14(OUTN)
NetR29_2: R29.2 U6.8(BUF)

Not connected (* = marked no-connect by the designer): U5 7(BSW)* 12(NC)* 20(NC)*

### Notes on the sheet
- +/-12V Analog
- (near TP6) +12Va @ 100mA
- (near TP8) -12Va @ 100mA

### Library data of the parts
C21 C28 C35 = CMP-0082267-1: as C2 on sheet PROC219_Power_IN_Dig
C22 C26 C31 C39 = CMP-0008802-2: CAP, CERM, 10 uF, 50 V, +/- 10%, X7R, 1206; Manufacturer: Samsung; TaMin_C: -55°C; Polarized: N; SizeAreaWB_mm2: 10.92; Value1: Unknown; U/M: EA; Value: 10uF; TaMax_C: 125°C; SizeZ_mm: 1.8; SizeX_mm: 3.2; SizeY_mm: 1.6; Cap_Case: 1206; Value2: 50V; SizeArea_mm2: 5.12; Cap_F: 10µF; AEC Category: Q200
C23 = CMP-0006488-2: CAP, CERM, 6.8 pF, 50 V, +/- 5%, C0G/NP0, 0402; Manufacturer: MuRata; TaMin_C: -55°C; Polarized: N; SizeAreaWB_mm2: 3; Value1: Unknown; U/M: EA; Value: 6.8pF; TaMax_C: 125°C; SizeZ_mm: 0.6; SizeX_mm: 1; SizeY_mm: 0.5; Value2: 50V; AEC Category: Q200
C24 C32 C36 C38 = CMP-0052806-1: as C20 on sheet PROC219_Power_IN_Dig
C25 C37 = CMP-0007040-4: as C1 on sheet PROC219_Power_IN_Dig
C27 = CMP-0006293-2: CAP, CERM, 0.22 uF, 16 V, +/- 10%, X7R, 0402; Manufacturer: TDK; TaMin_C: -55°C; Polarized: N; SizeAreaWB_mm2: 3; Value1: Unknown; U/M: EA; Value: 0.22uF; TaMax_C: 125°C; SizeZ_mm: 0.6; SizeX_mm: 1; SizeY_mm: 0.5; Value2: 16V; Cap_F: 220nF; AEC Category: Q200
C29 C33 = CMP-0860555-1: as C8 on sheet PROC219_Power_IN_Dig
C30 = CMP-0006482-2: CAP, CERM, 5.6 pF, 50 V, +/- 5%, C0G/NP0, 0402; Manufacturer: MuRata; TaMin_C: -55°C; Polarized: N; SizeAreaWB_mm2: 3; Value1: Unknown; U/M: EA; Value: 5.6pF; TaMax_C: 125°C; SizeZ_mm: 0.6; SizeX_mm: 1; SizeY_mm: 0.5; Value2: 50V; AEC Category: Q200
C34 = CMP-0115376-1: WCAP-CSGP Multilayer Ceramic Chip Capacitor, General Purpose, size 0402, X7R, 4.7nF, 50VDC; Manufacturer: Wurth Elektronik; Capacitance Tolerance: +/-10%; Dissipation Factor: 2.5%; Insulation Resistance: 10GOhm; Rated Voltage (DC): 50V; Technical Reference: X7R0402472K050DFCT10000
D7 D11 = CMP-0001466-1: Diode 40 V 2A Surface Mount SOD-123FL; Manufacturer: Panjit; AEC Qualified: No; SizeZ_mm: 1.1mm; TJmax_C: 150°C; Vf_V: 40V; Max Surge Forward Current: 50A; Peak Reverse Current: 100uA
D8 D10 = CMP-0028526-2: Diode, Schottky, 40 V, 0.5 A, SOD-123; Manufacturer: ON Semiconductor; Green_REACh: Passed; SizeY_mm: 1.7; Io_A: 500mA; SizeArea_mm2: 6.545; RJC_CperW: 118; Green_Lifecycle: Active; Vr_V: 40V; Vf_V: 510mV; TJmax_C: 150°C; AEC Category: Q101; SizeAreaWB_mm2: 13.095; Value1: 0.5A; SizeZ_mm: 1.35; SizeX_mm: 3.85; Value2: 0.51V; Value: 40V
D9 D12 = CMP-0076928-2: Diode, Schottky, 40 V, 0.35 A, SOD-323; Manufacturer: Micro Commercial Components; Value: 40V; SizeX_mm: 2.7; SizeAreaWB_mm2: 8.695; AEC Category: Q101; Vf_V: 600mV; SizeArea_mm2: 3.645; Green_Lifecycle: Not Set; SizeY_mm: 1.35; Io_A: 350mA; SizeZ_mm: 1.0; Green_REACh: Incomplete; Value2: 0.6V; Value1: 0.35A
L6 L8 = CMP-0063804-1: Inductor, Shielded Drum Core, Ferrite, 10 uH, 1 A, 0.12 ohm, SMD; Manufacturer: Wurth Elektronik; Isat: 1A @ 35% inductance drop; Irms: 1.3A @ 30C rise; Green_Lifecycle: Active; SizeAreaWB_mm2: 33.64; DCR_ohm: 0.12; Green_REACh: Passed; Value: 10uH; Imax_A: 1A; SizeZ_mm: 1.8; SizeX_mm: 4.8; SizeArea_mm2: 23.04; Ind_H: 10µH; AEC Category: Q200
L7 = CMP-0003140-1: as L4 on sheet PROC219_Power_IN_Dig
R20 = CMP-0123016-1: Res Thick Film 0402 91K Ohm 1% 0.063W(1/16W) ±100ppm/C Pad SMD T/R; Manufacturer: YAGEO; AEC Qualified: No; Power_W: 63mW; SizeZ_mm: 0.4mm; TempCo: 100ppm/°C; VDC_V: 50V
R21 = CMP-0026615-3: RES, 976 k, 1%, 0.063 W, AEC-Q200 Grade 0, 0402; Manufacturer: Vishay-Dale; Power_W: 63mW; TempCo: 100 ppm/C; Value: 976k; EIA_Code: E96; SizeX_mm: 1; SizeY_mm: 0.5; SizeZ_mm: 0.6; Value2: 0.063W; AEC Qualified: Y; VDC_V: 50V; AEC Category: Q200; AEC Grade: 0
R22 = CMP-0026609-3: RES, 93.1 k, 1%, 0.063 W, AEC-Q200 Grade 0, 0402; Manufacturer: Vishay-Dale; VDC_V: 50V; Value: 93.1k; SizeArea_mm2: 0.5; SizeX_mm: 1; AEC Qualified: Y; Value_Code: 93k1; EIA_Code: E96; AEC Category: Q200; TempCo: 100 ppm/C; Value2: 0.063W; AEC Grade: 0; SizeZ_mm: 0.6; Power_W: 63mW
R23 R27 R29 = CMP-0026658-1: as R9 on sheet PROC219_Power_IN_Dig
R24 = CMP-0120089-1: 68 kOhms ±1% 0.063W, 1/16W Chip Resistor 0402 (1005 Metric) Thick Film; Manufacturer: Walsin Technology; AEC Qualified: No; Power_W: 63mW; SizeZ_mm: 0.4mm; TempCo: 100ppm/°C; VDC_V: 50V
R25 = CMP-0026549-2: RES, 787 k, 1%, 0.063 W, AEC-Q200 Grade 0, 0402; Manufacturer: Vishay-Dale; Power_W: 63mW; TempCo: 100 ppm/C; Value: 787k; EIA_Code: E96; SizeX_mm: 1; SizeY_mm: 0.5; SizeZ_mm: 0.6; Value2: 0.063W; AEC Qualified: Y; VDC_V: 50V; AEC Category: Q200; AEC Grade: 0
R26 = CMP-0026656-1: RES, 100, 1%, 0.1 W, 0402; Manufacturer: Panasonic; Power_W: 100mW; TempCo: 100 ppm/C; Value_Code: 100R; U/M: EA; Value: 100; EIA_Code: E96; SizeX_mm: 1; SizeY_mm: 0.5; SizeZ_mm: 0.6; Value2: 0.1W; VDC_V: 50V; AEC Category: Q200
R28 = CMP-0026721-1: RES, 100 k, 1%, 0.0625 W, 0402; Manufacturer: Yageo America; Power_W: 62.5mW; TempCo: 100 ppm/C; U/M: EA; Value: 100k; EIA_Code: E96; SizeX_mm: 1; SizeY_mm: 0.5; SizeZ_mm: 0.6; AEC Qualified: N; VDC_V: 50V; AEC Category: Q200
TP5-TP8 = CMP-0003825-1: 1mm Test Point, SMT; Manufacturer: Any
U5 = CMP-0034952-2: Postive and Negative Output DC-DC Converter, 2.7 to 5.5 V, -40 to 85 degC, 24-pin QFN (RGE24), Green (RoHS & no Sb/Br); Manufacturer: Texas Instruments; SubFamily: LCD/OLED Display Bias Solutions; Rating: Catalog; Topology: Boost, Inverting Buck/Boost; Vin(Max)(V): 5.5; Vin(Min)(V): 2.7; Iq(Typ)(mA): 0.5; Switching Frequency(Typ)(kHz): 1400
U6 = CMP-0013435-7: Dual, 150mA, Wide-Vin, Positive and Negative Low-Dropout (LDO) Voltage Regulator, DSC0010J (WSON-10); Alternate Manufacturer: Texas Instruments; Alternate PartNumber: TPS7A3901DSCT; Rating: Catalog; CompType: IC; SizeAreaWB_mm2: 16.0; SizeY_mm: 3.0; AEC Qualified: N; SizeZ_mm: 0.8; SizeArea_mm2: 9.0; AEC Category: Q200

## Sheet PROC219_MSPM0.SchDoc
size 431 x 279 mm; Date: Not shown in title block; ApprovedBy: Not shown in title block; CheckedBy: Not shown in title block; Author: Not shown in title block; CompanyName: Not shown in title block; Engineer: Not shown in title block; Organization: Not shown in title block; Address1: Not shown in title block; Address2: Not shown in title block; Address3: Not shown in title block; Address4: Not shown in title block; DocumentNumber: 2; Revision: Use project parameter SCH_Rev; SheetNumber: 4; SheetTotal: 16; PageSetup: Record=PageOptions¦CenterHorizontal=True¦CenterVertical=True¦PrintScale=1.00¦XCorrection=1.00¦YCorrection=1.00¦PrintKind=0¦BorderSize=5000000¦LeftOffset=0¦BottomOffset=0¦Orientation=2¦PaperLength=1000¦PaperWidth=1000¦Scale=100¦PaperSource=15¦PrintQuality=600¦MediaType=1¦DitherType=10¦PaperKind=Letter¦PrintScaleMode=1
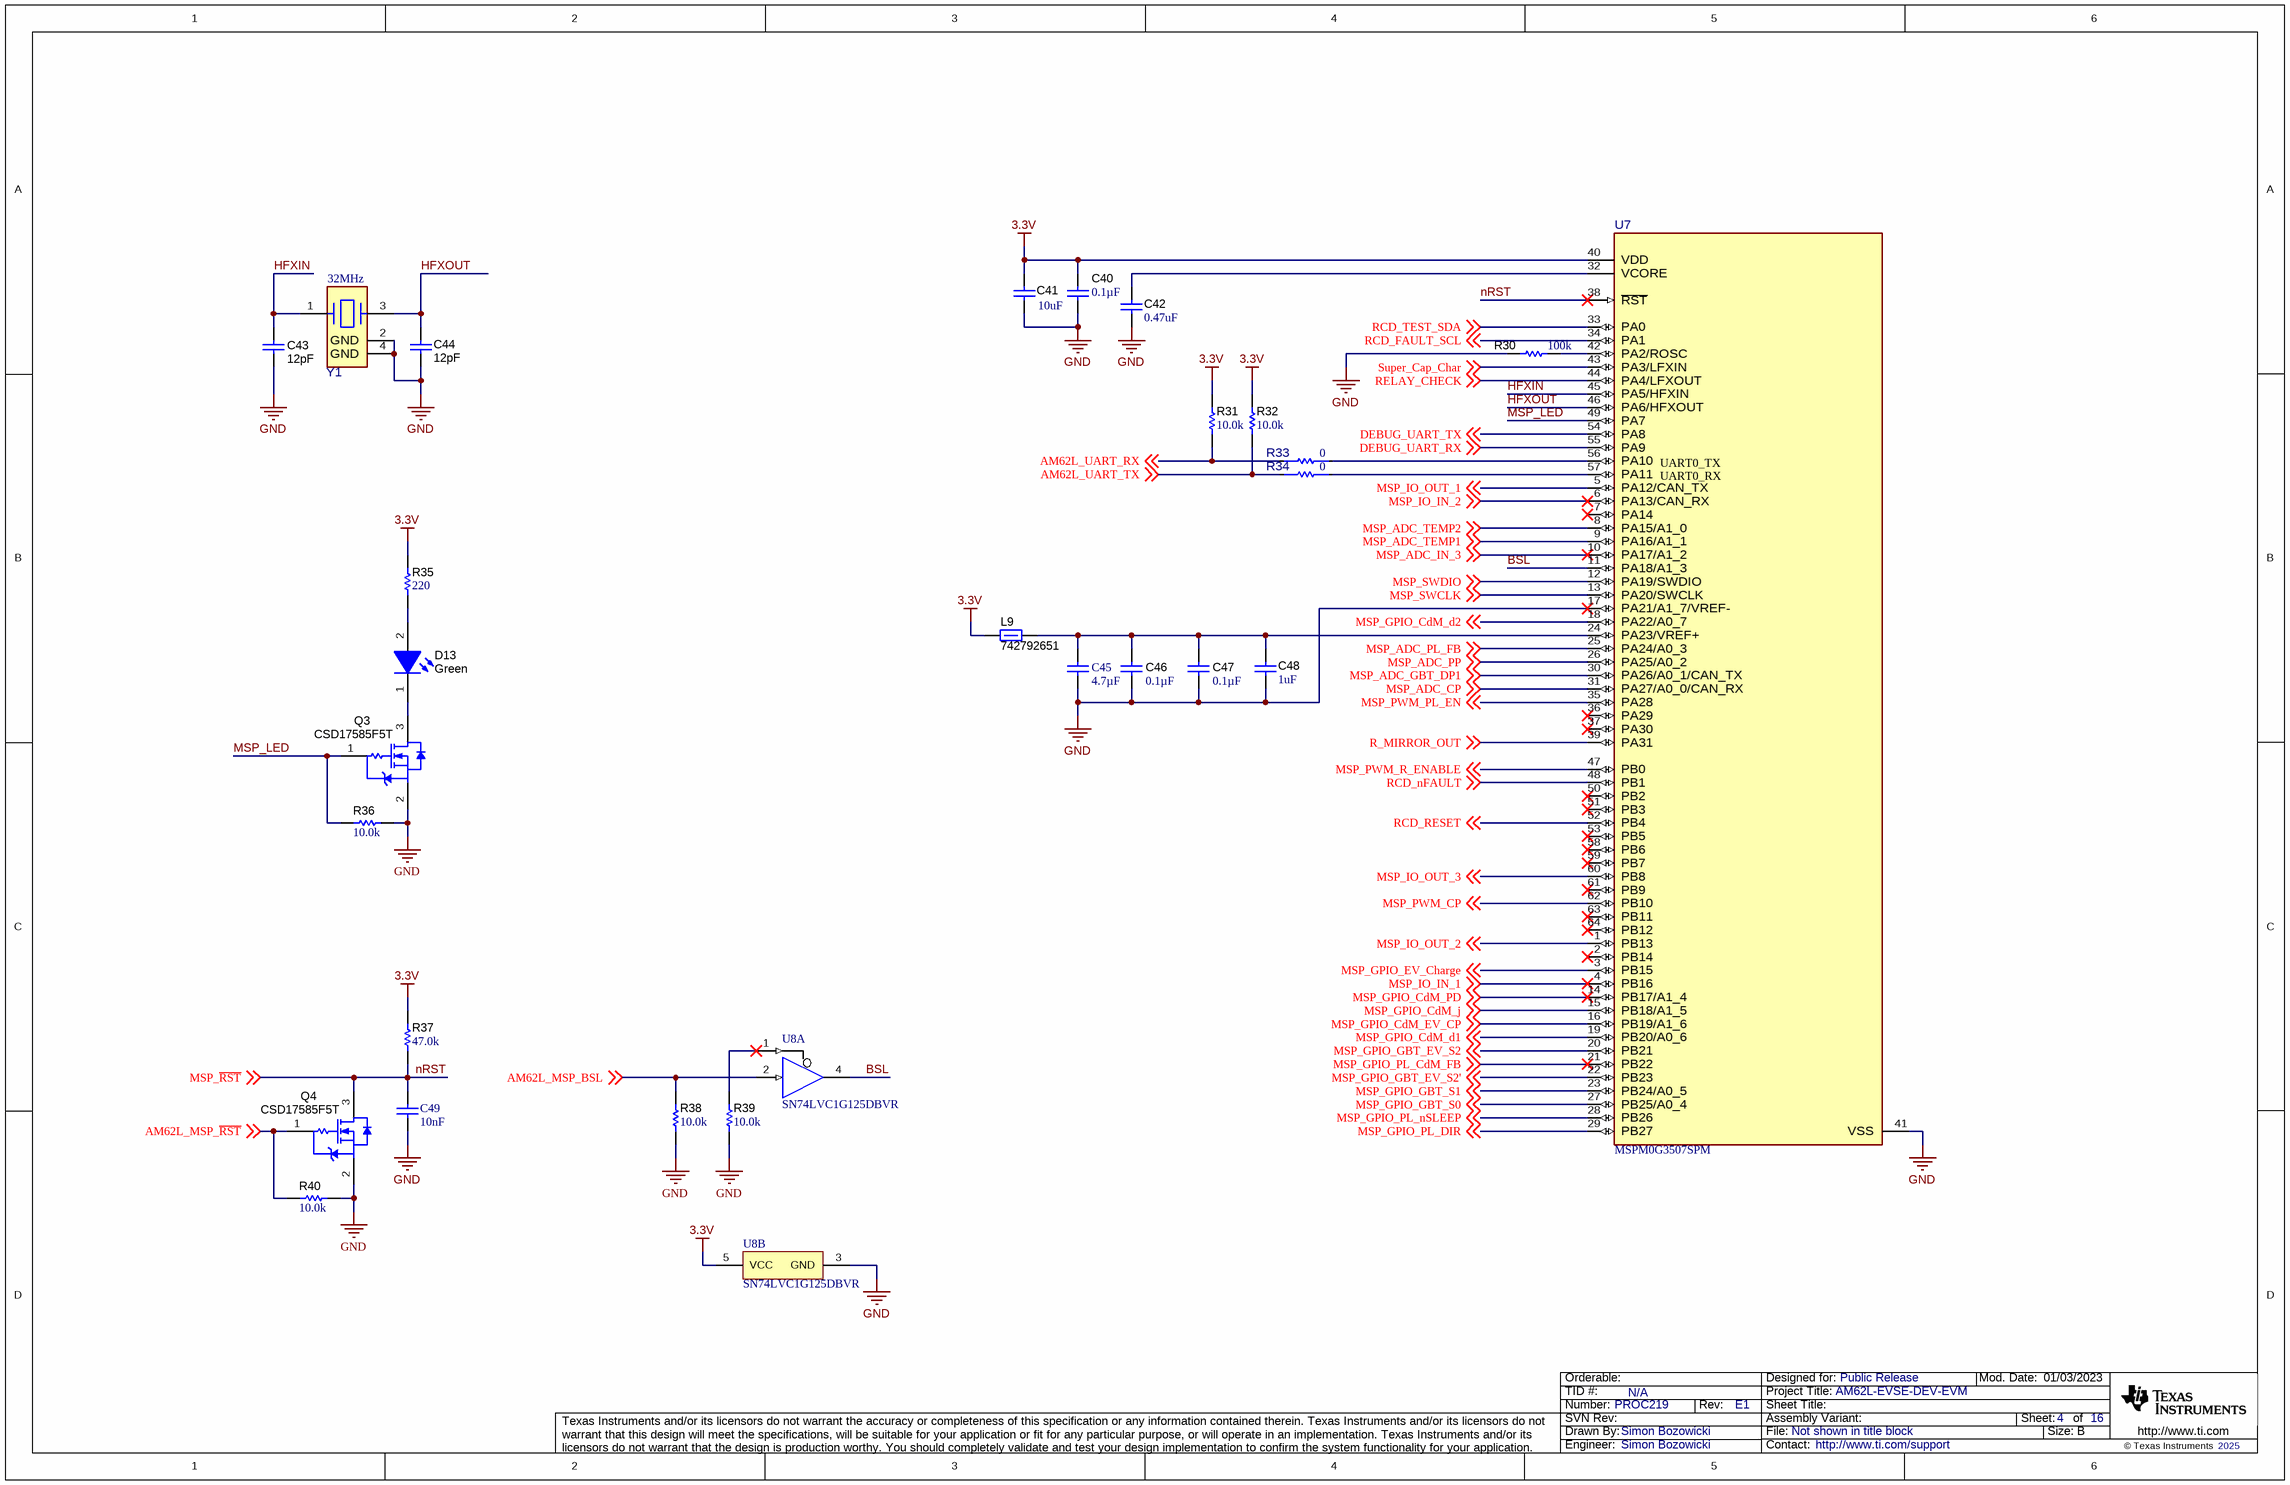
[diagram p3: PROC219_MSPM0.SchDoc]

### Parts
C40  ValueDisplayed: 0.1µF  [0402]  (hidden comment: CC0402KRX7R8BB104)
C41  ValueDisplayed: 10uF  [0603]  (hidden comment: C1608X5R1E106M080AC)
C42  ValueDisplayed: 0.47uF  [0402]  (hidden comment: GRM155R60J474KE19D)
C43  ValueDisplayed: 12pF  [0402]  (hidden comment: GRM1555C1H120JA01D)
C44  ValueDisplayed: 12pF  [0402]  (hidden comment: GRM1555C1H120JA01D)
C45  value 4.7µF  [WCAP-CSGP_0402_L1W0.5H0.5]  (hidden comment: 885012105008)
C46  ValueDisplayed: 0.1µF  [0402]  (hidden comment: CC0402KRX7R8BB104)
C47  ValueDisplayed: 0.1µF  [0402]  (hidden comment: CC0402KRX7R8BB104)
C48  ValueDisplayed: 1uF  [0402]  (hidden comment: C1005X7S1A105K050BC)
C49  value 10nF  [WCAP-CSGP_0402_L1W0.5H0.5]  (hidden comment: 885012205050)
D13  value Green  [WL-SMCW_GREEN]  (hidden comment: 150060VS75000)
L9  742792651  [0603]
Q3  CSD17585F5T  [YJK0003A]
Q4  CSD17585F5T  [YJK0003A]
R30  ValueDisplayed: 100k  [0402]  (hidden comment: RC0402FR-07100KL)
R31  ValueDisplayed: 10.0k  [0402]  (hidden comment: ERJ-2RKF1002X)
R32  ValueDisplayed: 10.0k  [0402]  (hidden comment: ERJ-2RKF1002X)
R33  value 0  [FP-CRG0402ZR_0402-IPC_C]  (hidden comment: CRG0402ZR)
R34  value 0  [FP-CRG0402ZR_0402-IPC_C]  (hidden comment: CRG0402ZR)
R35  ValueDisplayed: 220  [0402]  (hidden comment: CRCW0402220RJNED)
R36  ValueDisplayed: 10.0k  [0402]  (hidden comment: ERJ-2RKF1002X)
R37  ValueDisplayed: 47.0k  [0402]  (hidden comment: RC0402FR-0747KL)
R38  ValueDisplayed: 10.0k  [0402]  (hidden comment: ERJ-2RKF1002X)
R39  ValueDisplayed: 10.0k  [0402]  (hidden comment: ERJ-2RKF1002X)
R40  ValueDisplayed: 10.0k  [0402]  (hidden comment: ERJ-2RKF1002X)
U7  MSPM0G3507SPM  [PM0064A-MFG]
U8  SN74LVC1G125DBVR  [DBV0005A_N]  (parts A,B of 2)
Y1  Frequency_Fixed: 32MHz  [FP-830103622909_SMT_CRYSTAL_3MM4_2MM7-MFG]  (hidden comment: 830103622909)

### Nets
3.3V: C40.1 C41.1 L9.1 R31.2 R32.2 R35.2 R37.2 U7.40(VDD) U8.5(VCC)
GND: C40.2 C41.2 C42.2 C43.1 C44.2 C45.1 C46.2 C47.2 C48.1 C49.2 Q3.2(S) Q4.2(S) R30.1 R36.2 R38.1 R39.1 R40.2 U7.17(PA21/A1_7/VREF-) U7.41(VSS) U8.3(GND) Y1.2(GND) Y1.4(GND)
AM62L_MSP_BSL: R38.2 U8.2(A) ; off-sheet AM62L_MSP_BSL
AM62L_MSP_~{RST}: Q4.1(G) R40.1 ; off-sheet AM62L_MSP_~{RST}
AM62L_UART_RX: R31.1 R33.2 ; off-sheet AM62L_UART_RX
AM62L_UART_TX: R32.1 R34.2 ; off-sheet AM62L_UART_TX
BSL: U7.11(PA18/A1_3) U8.4(Y)
DEBUG_UART_RX: U7.55(PA9) ; off-sheet DEBUG_UART_RX  [project net MSP_DEBUG_UART_RX]
DEBUG_UART_TX: U7.54(PA8) ; off-sheet DEBUG_UART_TX  [project net MSP_DEBUG_UART_TX]
HFXIN: C43.2 U7.45(PA5/HFXIN) Y1.1(1_Crystal)
HFXOUT: C44.1 U7.46(PA6/HFXOUT) Y1.3(2_Crystal)
MSP_ADC_CP: U7.31(PA27/A0_0/CAN_RX) ; off-sheet MSP_ADC_CP
MSP_ADC_GBT_DP1: U7.30(PA26/A0_1/CAN_TX) ; off-sheet MSP_ADC_GBT_DP1
MSP_ADC_IN_3: U7.10(PA17/A1_2) ; off-sheet MSP_ADC_IN_3
MSP_ADC_PL_FB: U7.25(PA24/A0_3) ; off-sheet MSP_ADC_PL_FB  [project net PL_FB]
MSP_ADC_PP: U7.26(PA25/A0_2) ; off-sheet MSP_ADC_PP
MSP_ADC_TEMP1: U7.9(PA16/A1_1) ; off-sheet MSP_ADC_TEMP1  [project net P_TEMP1]
MSP_ADC_TEMP2: U7.8(PA15/A1_0) ; off-sheet MSP_ADC_TEMP2  [project net P_TEMP2]
MSP_GPIO_CdM_d1: U7.19(PB20/A0_6) ; off-sheet MSP_GPIO_CdM_d1
MSP_GPIO_CdM_d2: U7.18(PA22/A0_7) ; off-sheet MSP_GPIO_CdM_d2
MSP_GPIO_CdM_EV_CP: U7.16(PB19/A1_6) ; off-sheet MSP_GPIO_CdM_EV_CP
MSP_GPIO_CdM_j: U7.15(PB18/A1_5) ; off-sheet MSP_GPIO_CdM_j
MSP_GPIO_CdM_PD: U7.14(PB17/A1_4) ; off-sheet MSP_GPIO_CdM_PD
MSP_GPIO_EV_Charge: U7.3(PB15) ; off-sheet MSP_GPIO_EV_Charge
MSP_GPIO_GBT_EV_S2: U7.20(PB21) ; off-sheet MSP_GPIO_GBT_EV_S2
MSP_GPIO_GBT_EV_S2': U7.22(PB23) ; off-sheet MSP_GPIO_GBT_EV_S2'
MSP_GPIO_GBT_S0: U7.27(PB25/A0_4) ; off-sheet MSP_GPIO_GBT_S0
MSP_GPIO_GBT_S1: U7.23(PB24/A0_5) ; off-sheet MSP_GPIO_GBT_S1
MSP_GPIO_PL_CdM_FB: U7.21(PB22) ; off-sheet MSP_GPIO_PL_CdM_FB
MSP_GPIO_PL_DIR: U7.29(PB27) ; off-sheet MSP_GPIO_PL_DIR
MSP_GPIO_PL_nSLEEP: U7.28(PB26) ; off-sheet MSP_GPIO_PL_nSLEEP
MSP_IO_IN_1: U7.4(PB16) ; off-sheet MSP_IO_IN_1
MSP_IO_IN_2: U7.6(PA13/CAN_RX) ; off-sheet MSP_IO_IN_2
MSP_IO_OUT_1: U7.5(PA12/CAN_TX) ; off-sheet MSP_IO_OUT_1
MSP_IO_OUT_2: U7.1(PB13) ; off-sheet MSP_IO_OUT_2
MSP_IO_OUT_3: U7.60(PB8) ; off-sheet MSP_IO_OUT_3
MSP_LED: Q3.1(G) R36.1 U7.49(PA7)
MSP_PWM_CP: U7.62(PB10) ; off-sheet MSP_PWM_CP
MSP_PWM_PL_EN: U7.35(PA28) ; off-sheet MSP_PWM_PL_EN
MSP_PWM_R_ENABLE: U7.47(PB0) ; off-sheet MSP_PWM_R_ENABLE
MSP_~{RST}: C49.1 Q4.3(D) R37.1 U7.38(~{RST}) ; off-sheet MSP_~{RST}  [also labelled nRST]
MSP_SWCLK: U7.13(PA20/SWCLK) ; off-sheet MSP_SWCLK  [project net PA20_SWCLK]
MSP_SWDIO: U7.12(PA19/SWDIO) ; off-sheet MSP_SWDIO  [project net PA19_SWDIO]
R_MIRROR_OUT: U7.39(PA31) ; off-sheet R_MIRROR_OUT
RCD_FAULT_SCL: U7.34(PA1) ; off-sheet RCD_FAULT_SCL
RCD_nFAULT: U7.48(PB1) ; off-sheet RCD_nFAULT
RCD_RESET: U7.52(PB4) ; off-sheet RCD_RESET
RCD_TEST_SDA: U7.33(PA0) ; off-sheet RCD_TEST_SDA
RELAY_CHECK: U7.44(PA4/LFXOUT) ; off-sheet RELAY_CHECK
Super_Cap_Char: U7.43(PA3/LFXIN) ; off-sheet Super_Cap_Char
NetC42_1: C42.1 U7.32(VCORE)
NetC45_2: C45.2 C46.1 C47.1 C48.2 L9.2 U7.24(PA23/VREF+)
NetD13_1: D13.1(K) Q3.3(D)
NetD13_2: D13.2(A) R35.1
NetR30_2: R30.2 U7.42(PA2/ROSC)
NetR33_1: R33.1 U7.56(PA10)
NetR34_1: R34.1 U7.57(PA11)
NetR39_2: R39.2 U8.1(~{OE})

Not connected (* = marked no-connect by the designer): U7 2(PB14)* 7(PA14)* 36(PA29)* 37(PA30)* 50(PB2)* 51(PB3)* 53(PB5)* 58(PB6)* 59(PB7)* 61(PB9)* 63(PB11)* 64(PB12)*

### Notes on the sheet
- (near U7) UART0_RX
- (near U7) UART0_TX

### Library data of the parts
C40 C46 C47 = CMP-0860555-1: as C8 on sheet PROC219_Power_IN_Dig
C41 = CMP-0007007-5: CAP, CERM, 10 uF, 25 V, +/- 20%, X5R, 0603; Manufacturer: TDK; TaMin_C: -55°C; ESR_ohm: 4.639m; Polarized: N; SizeAreaWB_mm2: 4.68; Value1: 0.004639 ohm; U/M: EA; Value: 10uF; TaMax_C: 85°C; SizeZ_mm: 1; SizeX_mm: 1.6; SizeY_mm: 0.8; Value2: 25V; SizeArea_mm2: 1.28; Cap_F: 10µF; IRMS_A: 2.41407A; AEC Category: Q200
C42 = CMP-0006551-2: CAP, CERM, 0.47 uF, 6.3 V, +/- 10%, X5R, 0402; Manufacturer: MuRata; TaMin_C: -55°C; Polarized: N; SizeAreaWB_mm2: 3; Value1: Unknown; U/M: EA; Value: 0.47uF; TaMax_C: 85°C; SizeZ_mm: 0.6; SizeX_mm: 1; SizeY_mm: 0.5; Value2: 6.3V; Cap_F: 470nF; AEC Category: Q200
C43 C44 = CMP-0006415-2: CAP, CERM, 12 pF, 50 V, +/- 5%, C0G/NP0, 0402; Manufacturer: MuRata; TaMin_C: -55°C; Polarized: N; SizeAreaWB_mm2: 3; Value1: Unknown; U/M: EA; Value: 12pF; TaMax_C: 125°C; SizeZ_mm: 0.6; SizeX_mm: 1; SizeY_mm: 0.5; Value2: 50V; AEC Category: Q200
C45 = CMP-0104471-1: WCAP-CSGP Multilayer Ceramic Chip Capacitor, General Purpose, size 0402, X5R, 4.7µF, 6.3VDC; Manufacturer: Wurth Elektronik; Capacitance Tolerance: +/-20%; Dissipation Factor: 10%; Insulation Resistance: 0.02GOhm; Rated Voltage (DC): 6.3V; Technical Reference: X5R0402475M6R3DFCT10000
C48 = CMP-0006300-2: CAP, CERM, 1 uF, 10 V, +/- 10%, X7S, 0402; Manufacturer: TDK; TaMin_C: -55°C; ESR_ohm: 0.011416; Polarized: N; SizeAreaWB_mm2: 3; Value1: 0.011416 ohm; U/M: EA; Value: 1uF; TaMax_C: 125°C; SizeZ_mm: 0.6; SizeX_mm: 1; SizeY_mm: 0.5; Value2: 10V; Cap_F: 1µF; IRMS_A: 1.483A; AEC Category: Q200
C49 = CMP-0052806-1: as C20 on sheet PROC219_Power_IN_Dig
D13 = CMP-0002894-2: as D5 on sheet PROC219_Power_IN_Dig
L9 = CMP-0003197-2: Ferrite Bead, 600 ohm @ 100 MHz, 1 A, 0603; Manufacturer: Wurth Elektronik; Ztyp@1GHz_Ohm: 257.548; ZTyp@100MHz_Ohm: 600; SizeAreaWB_mm2: 4.68; DCR_ohm: 2d; Value1: 0.2 ohm; Value: 600 ohm; Imax_A: 1A; SizeZ_mm: 1; SizeX_mm: 1.6; SizeY_mm: 0.8; SizeArea_mm2: 1.28
Q3 Q4 = CMP-0067551-1: as Q1 on sheet PROC219_Power_IN_Dig
R30 = CMP-0026721-1: as R28 on sheet PROC219_Power_Analog
R31 R32 R36 R38-R40 = CMP-0026658-1: as R9 on sheet PROC219_Power_IN_Dig
R33 R34 = CMP-0095664-1: as R8 on sheet PROC219_Power_IN_Dig
R35 = CMP-0026878-3: RES, 220, 5%, 0.063 W, AEC-Q200 Grade 0, 0402; Manufacturer: Vishay-Dale; Power_W: 63mW; TempCo: 200 ppm/C; Value_Code: 220R; Value: 220; EIA_Code: E24; SizeX_mm: 1; SizeY_mm: 0.5; SizeZ_mm: 0.6; Value2: 0.063W; AEC Qualified: Y; VDC_V: 50V; AEC Category: Q200; AEC Grade: 0
R37 = CMP-0026737-1: as R6 on sheet PROC219_Power_IN_Dig
U7 = CMP-0093960-1: Mixed-Signal Microcontrollers With CAN-FD Interface LQFP64; Manufacturer: Texas Instruments; Number Of I2C Channels: 2; Frequency_Fixed: 80MHz; Number Of Cores: 1; Number Of Pwm Channels: 14; Data Bus Width: 32bits; Standoff Height: 0.05mm; SizeZ_mm: 1.6mm; Number Of I/Os: 60; Memory Type: FLASH; Min Supply Voltage: 1.62V; Number Of Adc Channels: 16; Memory Size: 128KBytes; TJmax_C: +130°C; Number Of Uart Channels: 4; Number Of Timers/Counters: 7; Max Supply Voltage: 3.6V; TaMin_C: -40°C; Core Architecture: ARM Cortex-M0+; Interface: I2C,SPI,UART,CAN,LIN,IrDA,SMBus; Ram Size: 32KBytes; AEC Qualified: No; TaMax_C: +125°C
U8 = CMP-0051300-2: Single Bus Buffer Gate With 3-State Outputs, DBV0005A, LARGE T&R; Manufacturer: Texas Instruments; VCC(Min)(V): 1.65; Sub-Family: Non-Inverting Buffer/Driver; tpd @ Nom Voltage(Max)(ns): 9,5.5,4.5,4; Input Type: CMOS/TTL; ICC @ Nom Voltage(Max)(mA): 0.01; Schmitt Trigger: No; Voltage(Nom)(V): 1.8,2.5,3.3,5; F @ Nom Voltage(Max)(Mhz): 150; Output Drive (IOL/IOH)(Max)(mA): 32/-32; 3-State Output: Yes; Output Type: CMOS; Bits(#): 1; Rating: Catalog; Technology Family: LVC; Logic: True; VCC(Max)(V): 5.5; AEC Category: Q200; AEC Qualified: N; CompType: IC
Y1 = CMP-0124814-1: 32 MHz ±10ppm Crystal 9pF 40 Ohms 4-SMD, No Lead; Manufacturer: Wurth Electronics; SizeZ_mm: 0.8mm; Esr: 40; Frequency Stability: 15ppm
